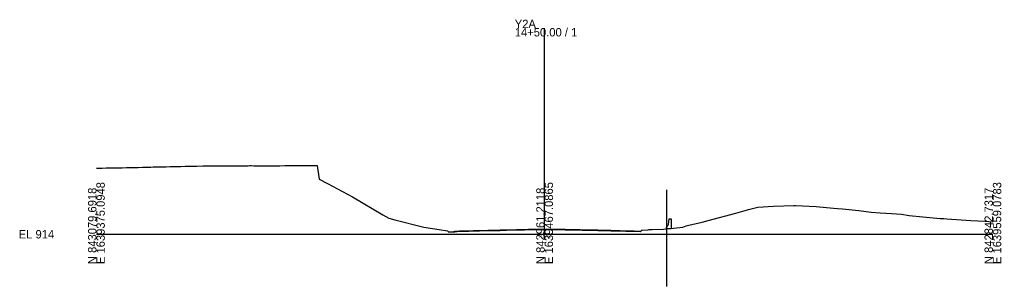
# Model space of a CAD drawing. Extents: x -26 to 303, y -10 to 10517.
# Drawn here: x -25.7 to 302.8, y 3982.5 to 4071.9 of the extents above; entities that cross this region are included whole.
import ezdxf

# ---------------------------------------------------------------- set-up
doc = ezdxf.new("R2010")
doc.units = 0
for name, color, linetype in [('Exist Cross Section Cell', 7, 'Continuous'), ('Exist XS Center Line Elevation Label', 7, 'Continuous'), ('Exist XS Ground Line', 7, 'Continuous'), ('Prop CMT Pvmt Surface Overlay', 7, 'Continuous'), ('Scratch_Level_0', 7, 'Continuous'), ('Typical Median Barrier CELL', 7, 'Continuous')]:
    doc.layers.add(name, color=color, linetype=linetype)

msp = doc.modelspace()

# ---------------------------------------------------------------- linework, layer by layer
at = {"layer": 'Exist Cross Section Cell'}
for p, q in [((150, 4000), (150, 4069.1)), ((0, 4000), (150, 4000)), ((150, 4000), (300, 4000))]:
    msp.add_line(p, q, dxfattribs=at)
at = {"layer": 'Exist XS Ground Line'}
msp.add_lwpolyline([(0, 4022.15), (1.19, 4022.18), (1.49, 4022.18), (1.88, 4022.19), (3.28, 4022.21), (4.36, 4022.23), (5.06, 4022.25), (5.96, 4022.26), (6.84, 4022.28), (7.52, 4022.29), (8.62, 4022.31), (10.04, 4022.34), (10.69, 4022.35), (12.95, 4022.39), (13.96, 4022.41), (15.44, 4022.45), (16.13, 4022.46), (17.02, 4022.48), (18.19, 4022.51), (19.03, 4022.54), (20.18, 4022.56), (22.27, 4022.61), (22.88, 4022.63), (23.35, 4022.64), (24.66, 4022.68), (26.51, 4022.73), (28.22, 4022.75), (29.68, 4022.79), (30.42, 4022.8), (32.84, 4022.85), (33.65, 4022.87), (35.57, 4022.91), (36.26, 4022.92), (38.17, 4022.91), (39.32, 4022.9), (40.33, 4022.9), (41.96, 4022.88), (42.34, 4022.9), (42.65, 4022.91), (44.51, 4022.92), (45.5, 4022.94), (46.72, 4022.94), (48.67, 4022.97), (50.29, 4022.98), (50.8, 4022.98), (51.38, 4022.99), (51.83, 4022.99), (52.71, 4022.98), (53.23, 4022.98), (54.63, 4022.97), (55, 4022.97), (55.42, 4022.97), (58.16, 4022.97), (58.95, 4022.97), (61.33, 4022.97), (63.03, 4023), (64.49, 4023), (67.11, 4023.01), (67.66, 4023.01), (69.2, 4023.01), (70.82, 4023.03), (71.18, 4023.03), (73.38, 4023.03), (73.85, 4023.03), (74.53, 4018.47), (77.34, 4016.97), (85.68, 4012.52), (95.87, 4006.54), (97.86, 4005.38), (99.82, 4004.87), (109.59, 4002.33), (114.71, 4001.6), (117.54, 4001.2), (117.98, 4000.73), (119.56, 4000.83), (119.99, 4000.85), (121.47, 4000.98), (124.18, 4001.06), (124.63, 4001.08), (126.21, 4001.12), (127.8, 4001.15), (128.25, 4001.17), (130.96, 4001.22), (131.77, 4001.24), (132.87, 4001.25), (134.13, 4001.28), (135.12, 4001.31), (136.41, 4001.35), (136.9, 4001.36), (137.29, 4001.38), (140.57, 4001.45), (142.8, 4001.5), (143.25, 4001.51), (144.56, 4001.54), (146.79, 4001.58), (148.64, 4001.6), (149.93, 4001.62), (151.56, 4001.6), (153.13, 4001.59), (153.53, 4001.58), (156.55, 4001.54), (156.92, 4001.52), (157.68, 4001.51), (159.45, 4001.47), (160.07, 4001.46), (160.87, 4001.44), (161.85, 4001.43), (162.61, 4001.41), (164.94, 4001.35), (165.78, 4001.34), (167.79, 4001.31), (168.24, 4001.29), (169.02, 4001.28), (172.11, 4001.2), (173.09, 4001.18), (174.32, 4001.15), (175.27, 4001.11), (177.17, 4001.06), (178.44, 4001.04), (180, 4000.98), (181.94, 4000.89), (182.57, 4001.37), (184.67, 4001.53), (185.03, 4001.56), (185.53, 4001.6), (185.98, 4001.61), (189.72, 4001.71), (193.11, 4002.03), (196.19, 4002.36), (197.41, 4002.77), (198.21, 4003.08), (202.72, 4004.06), (204.71, 4004.61), (214.01, 4007.1), (217.84, 4008.13), (218.19, 4008.25), (221.33, 4009.04), (226.62, 4009.43), (233.42, 4009.62), (233.99, 4009.61), (240.87, 4009.29), (246.65, 4008.77), (248, 4008.67), (249.73, 4008.49), (255.13, 4007.96), (259.32, 4007.45), (262.25, 4007.22), (266.04, 4006.93), (269.38, 4006.7), (271.98, 4006.33), (276.51, 4005.88), (282.34, 4005.3), (283.63, 4005.23), (284.64, 4005.19), (292.6, 4004.65), (297.3, 4004.39), (297.89, 4004.34), (298.65, 4004.27), (300, 4004.14)], dxfattribs=at)
at = {"layer": 'Prop CMT Pvmt Surface Overlay'}
msp.add_lwpolyline([(117.87, 4000.85), (119.55, 4000.95), (119.98, 4000.98), (121.46, 4001.11), (124.17, 4001.19), (124.63, 4001.2), (126.2, 4001.24), (127.79, 4001.28), (128.25, 4001.29), (130.96, 4001.35), (131.77, 4001.37), (132.87, 4001.38), (134.12, 4001.4), (135.12, 4001.43), (136.4, 4001.47), (136.9, 4001.49), (137.29, 4001.5), (140.57, 4001.57), (142.8, 4001.62), (143.24, 4001.63), (144.56, 4001.66), (146.78, 4001.71), (148.63, 4001.73), (149.93, 4001.74), (151.56, 4001.72), (153.13, 4001.71), (153.54, 4001.7), (156.55, 4001.66), (156.92, 4001.65), (157.68, 4001.63), (159.45, 4001.59), (160.07, 4001.58), (160.87, 4001.57), (161.85, 4001.55), (162.62, 4001.53), (164.94, 4001.48), (165.78, 4001.46), (167.79, 4001.43), (168.25, 4001.42), (169.02, 4001.41), (172.11, 4001.33), (173.1, 4001.3), (174.32, 4001.28), (175.28, 4001.24), (177.17, 4001.19), (178.44, 4001.16), (180, 4001.11), (182.09, 4001.01)], dxfattribs=at)
at = {"layer": 'Scratch_Level_0'}
msp.add_line((190.79, 4014.85), (190.79, 3982.52), dxfattribs=at)
at = {"layer": 'Typical Median Barrier CELL'}
for p, q in [((191.4, 4003.27), (191.62, 4005.22)), ((191.62, 4005.22), (192.29, 4005.22)), ((192.29, 4005.22), (192.29, 4001.81)), ((190.79, 4002.22), (191.25, 4002.88)), ((190.79, 4001.81), (190.79, 4002.22)), ((192.29, 4001.81), (190.79, 4001.81))]:
    msp.add_line(p, q, dxfattribs=at)
msp.add_arc((190.57, 4003.36), 0.833, 325.0039, 353.9447, dxfattribs=at)

# ---------------------------------------------------------------- texts
at = {"layer": 'Exist Cross Section Cell'}
for s, p in [('Y2A', (140, 4069.1)), ('14+50.00 / 1', (140, 4066.3)), ('EL 914', (-26, 3998.6))]:
    msp.add_text(s, height=2.8, dxfattribs=at).set_placement(p)
for s, p in [('N 843079.6918', (0, 3990)), ('E 1639375.0948', (2.8, 3990)), ('N 842961.2118', (150, 3990)), ('E 1639467.0865', (152.8, 3990)), ('N 842842.7317', (300, 3990)), ('E 1639559.0783', (302.8, 3990))]:
    msp.add_text(s, height=2.8, rotation=90, dxfattribs=at).set_placement(p)
at = {"layer": 'Exist XS Center Line Elevation Label'}
msp.add_text('915.62', height=1, dxfattribs=at).set_placement((147.89, 3998.98))

doc.saveas('drawing.dxf')
